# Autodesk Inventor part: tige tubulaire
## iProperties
Shininess: 43.0
Length Units: 11269
Angle Units: 11279
Time Units: 11290
Mass Units: 11283
Length Display Precision: 3
Angle Display Precision: 2
Created: 2002-06
Part Number: tige tubulaire
Material: Par défaut
Document SubType Name: Modélisation
Designer: REVEST Pierre
Density: 0.0
Volumn: 0.0
Area: 0.0
PropertySet Name: Model Information
Control State: 0
Master: False
Checked Out: False
Author: REVEST Pierre
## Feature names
1. Extrusion1
2. Extrusion3
